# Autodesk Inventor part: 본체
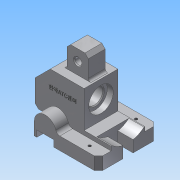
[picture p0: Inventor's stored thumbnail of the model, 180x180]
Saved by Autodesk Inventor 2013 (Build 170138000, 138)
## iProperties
Created: 2016-11
Part Number: 본체
Material: 알루미늄 6061
Document SubType Name: Modeling
Designer: Administrator
Density: 2.71 g/cm^3
Mass: 469.5 g
Surface Area: 321.838 cm^2
Volume: 173.247 cm^3
Author: Administrator
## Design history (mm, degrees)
sketch "스케치2"
  geometry: L1 (-38, -35)-(38, -35); L2 (38, -35)-(38, 35); L3 (38, 35)-(-38, 35); L4 (-38, 35)-(-38, -35); L5 (-38, -35)-(38, 35); L6 (38, -35)-(-38, 35); 2 further points
  constraints: 12 end point, 2 midpoint, 2 parallel, 1 coincident, 1 horizontal, 1 perpendicular
  dimensions: "d3" = 76 distance of L2.end L3.end; "d5" = 70 distance of L1.end L2.end
extrude "돌출1" new body sketch "스케치2" distance "d6" = 15; taper "d7" = 0 deg
sketch "스케치3"
  geometry: L1 (0, 15)-(76, 15) reference; L2 (0, 0)-(0, 15) reference; C1 r 13 at (13, 15); 1 further point
  constraints: 1 centre point, 1 point on line, 1 tangent
  dimensions: "d8" = 26 diameter of C1
extrude "돌출2" join sketch "스케치3" distance "d10" = 70; taper "d11" = 0 deg
fillet "모깎기1" dims "d12" = 5
sketch "스케치4"
  geometry: L1 (-7.708, -35)-(-7.708, 35) reference; L2 (38, -35)-(38, 35) reference; L3 (38, 20)-(-52, 20); L4 (-52, 20)-(-52, -20); L5 (-52, -20)-(38, -20); L6 (38, -20)-(38, 20); L7 (-7.708, 0)-(19.876, 0); 1 further point
  constraints: 10 end point, 2 parallel, 2 perpendicular, 1 horizontal, 1 midpoint, 1 point on line, 1 other
  dimensions: "d13" = 40 distance between parallel lines of L5 L3; "d15" = 90 distance between parallel lines of L2 L4
extrude "돌출3" join sketch "스케치4" distance "d16" = 75; taper "d17" = 0 deg
chamfer "모따기1" distance "d18" = 4; stored, may be unused: second distance "d19" = 2, angle "d20" = 45 deg
chamfer "모따기2" distance "d21" = 5; stored, may be unused: second distance "d22" = 2, angle "d23" = 45 deg
sketch "스케치5"
  geometry: L1 (0, 0)-(0, 15) reference; L2 (0, 0)-(71, 0) reference; L3 (3, 0)-(23, 0); L4 (23, 0)-(23, 7.634); L5 (23, 7.634)-(3, 7.634); L6 (3, 7.634)-(3, 0); 1 further point
  constraints: 8 end point, 2 parallel, 1 horizontal, 1 perpendicular, 1 point on line
  dimensions: "d24" = 3 distance between parallel lines of L6 L1; "d25" = 20 distance between parallel lines of L4 L6
extrude "돌출4" cut sketch "스케치5" stored distance "d26" = 75; taper "d27" = 0 deg
sketch "스케치6"
  geometry: L1 (-40.292, 0)-(-44.292, 4) reference; L2 (-40.292, 0)-(-30.292, 0) reference; L3 (45.708, 0)-(45.708, 75) reference; L4 (-44.292, 75)-(45.708, 75) reference; L5 (-44.292, 4)-(-44.292, 75) reference; L6 (-44.292, 30)-(-26.292, 48); L7 (-26.292, 48)-(-16.292, 48); L8 (-16.292, 48)-(-16.292, 75); L9 (8.708, 75)-(8.708, 48); L10 (8.708, 48)-(13.708, 48); L11 (13.708, 48)-(13.708, 5); L12 (13.708, 5)-(45.708, 5); L13 (-7.292, -15)-(40.708, -15) reference; 1 further point
  constraints: 14 end point, 4 perpendicular, 4 point on line, 3 parallel, 1 horizontal alignment
  dimensions: "d28" = 20 distance between parallel lines of L13 L12; "d30" = 5 distance between parallel lines of L11 L9; "d31" = 25 distance between parallel lines of L9 L8; "d32" = 18 horizontal distance of L6.start L6.end; "d33" = 58 distance between parallel lines of L5 L11; "d34" = 30 distance from line of L2 L6.start
extrude "돌출5" cut sketch "스케치6" distance "d35" = 75; taper "d36" = 0 deg
sketch "스케치7"
  geometry: L1 (0, 43)-(40, 43) reference; L2 (0, 70)-(40, 70) reference; L3 (40, 70)-(40, 43); L4 (0, 43)-(0, 70); L5 (10, 70)-(10, 43); L6 (30, 70)-(30, 43); L7 (0, 70)-(10, 70); L8 (30, 70)-(40, 70); L9 (40, 43)-(30, 43); L10 (10, 43)-(0, 43); 1 further point
  constraints: 16 end point, 5 parallel, 5 perpendicular, 2 horizontal
  dimensions: "d37" = 10 distance between parallel lines of L5 L4; "d39" = 10 distance between parallel lines of L3 L6
extrude "돌출6" cut sketch "스케치7" distance "d40" = 75; taper "d41" = 0 deg
chamfer "모따기3" distance "d42" = 4; stored, may be unused: second distance "d43" = 2, angle "d44" = 45 deg
fillet "모깎기2" dims "d45" = 3
sketch "스케치8"
  geometry: L1 (-4, -24)-(-4, -4) reference; L2 (5, -90)-(53, -90) reference; C1 r 4 at (8.5, -13); 1 further point
  constraints: 1 centre point
  dimensions: "d46" = 8 diameter of C1; "d48" = 12.5 distance from line of L1 C1.centre; "d49" = 77 distance from line of L2 C1.centre
extrude "돌출7" cut sketch "스케치8" distance "d50" = 75; taper "d51" = 0 deg
chamfer "모따기4" distance "d52" = 1; stored, may be unused: second distance "d53" = 2, angle "d54" = 45 deg
sketch "스케치9"
  geometry: L1 (-10, -20)-(50, -20) reference; C1 r 14.5 at (20, 22); 2 further points
  constraints: 1 centre point, 1 midpoint, 1 vertical alignment
  dimensions: "d55" = 29 diameter of C1; "d57" = 42 distance from line of L1 C1.centre
extrude "돌출8" cut sketch "스케치9" distance "d58" = 7; taper "d59" = 0 deg
sketch "스케치10"
  geometry: C1 r 14.5 at (0, 0) reference; C2 r 10 at (0, 0); 1 further point
  constraints: 1 centre point, 1 coincident
  dimensions: "d60" = 20 diameter of C2
extrude "돌출9" cut sketch "스케치10" stored distance "d62" = 7; taper "d63" = 0 deg
sketch "스케치11"
  geometry: L1 (0, 0)-(60, 0) reference; L2 (50, 15)-(50, 20) reference; L3 (30, 0)-(30, 6.76); L4 (24, 13.627)-(24, 0); L5 (36, 13.627)-(36, 0); C1 r 10 at (30, 42) reference; A1 r 29 centre (30, 42) between (24, 13.627) and (36, 13.627)
  constraints: 6 end point, 3 parallel, 2 point on circle, 2 point on line, 1 centre point, 1 coincident, 1 other
  dimensions: "d64" = 58 diameter of A1; "d66" = 12 distance between parallel lines of L5 L4
extrude "돌출10" cut sketch "스케치11" distance "d67" = 18; taper "d68" = 0 deg
chamfer "모따기5" distance "d69" = 1; stored, may be unused: second distance "d70" = 2, angle "d71" = 45 deg
sketch "스케치12"
  geometry: L1 (38, -30)-(38, -20) reference; L2 (-7.708, -35)-(33, -35) reference; L3 (38, -27.5)-(20, -27.5); 1 further point
  constraints: 2 end point, 1 parallel, 1 point on line
  dimensions: "d72" = 18 distance from line of L1 L3.end; "d73" = 7.5 distance between parallel lines of L2 L3
hole "구멍1" sketch "스케치12" at (20, -27.5) diameter "d74" = 3.242; stored, may be unused: countersink angle "d78" = 90 deg, drill point angle "d80" = 118 deg; dims "d75" = 6, "d76" = 4, "d77" = 2, "d79" = 8
sketch "스케치13"
  geometry: L1 (13.708, 48)-(-26.292, 48) reference; L2 (13.708, 5)-(13.708, 48) reference; L3 (-21.978, 32.148)-(-0.605, 32.148); L4 (-0.605, 32.148)-(-0.605, 27.852); L5 (-0.605, 27.852)-(-21.978, 27.852); L6 (-21.978, 27.852)-(-21.978, 32.148); L7 (-11.292, 32.148)-(-11.292, 27.852); L8 (-0.605, 30)-(-21.978, 30); 1 further point
  constraints: 4 end point, 4 midpoint, 2 other
  dimensions: "d85" = 25 distance from line of L2 L7.start; "d86" = 18 distance between parallel lines of L1 L8
feature "엠보싱1" sketch "스케치13" dims "d3" = 76, "d5" = 70, "d87" = 0.5, "d88" = 0
node "솔리드1"
pattern_linear "직사각형 패턴1" dims "d83" = 55
